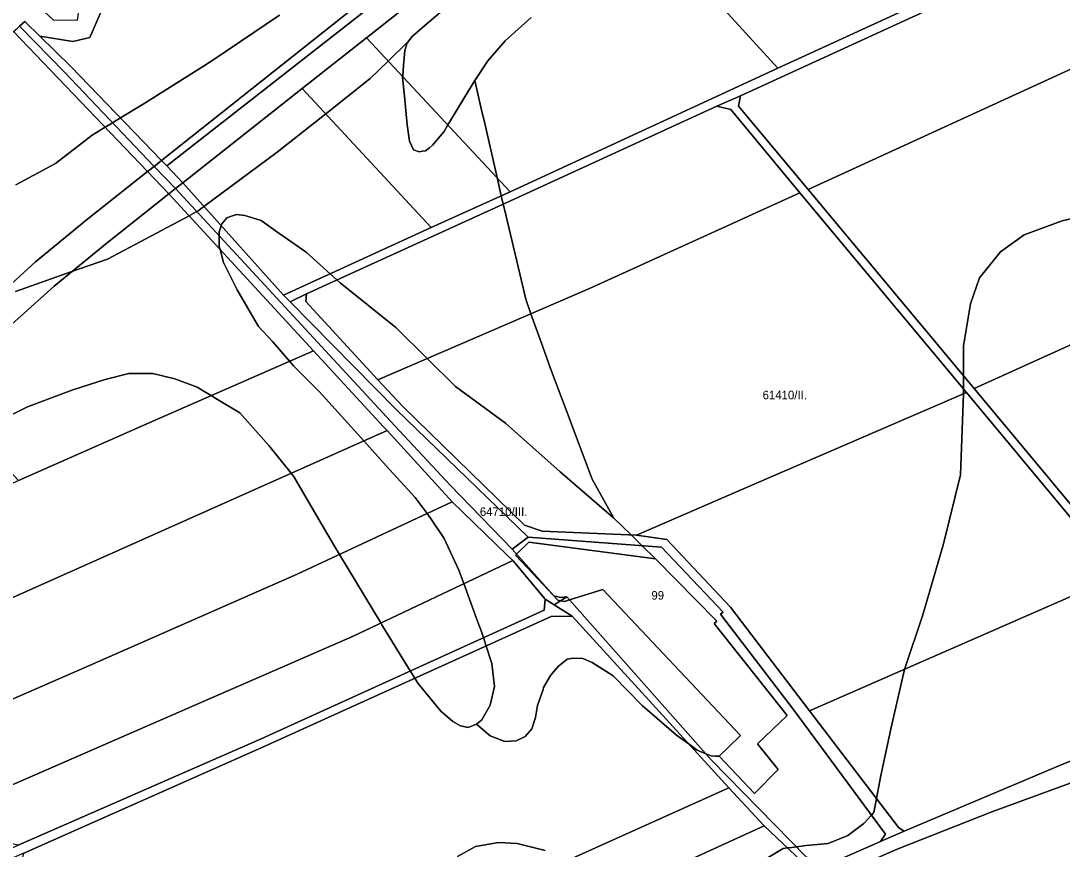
# Model space of a CAD drawing. Extents: x -522079 to -518833, y -1142400 to -1139961.
# Drawn here: x -521596 to -520985, y -1141010 to -1140524 of the extents above; entities that cross this region are included whole.
import ezdxf

# ---------------------------------------------------------------- set-up
doc = ezdxf.new("R2010")
doc.units = 0
for name, color, linetype in [('95560013', 7, 'Continuous'), ('95610013', 7, 'Continuous'), ('95620013', 7, 'Continuous'), ('95630013', 7, 'Continuous'), ('95640013', 7, 'Continuous'), ('95660013', 7, 'Continuous')]:
    doc.layers.add(name, color=color, linetype=linetype)

msp = doc.modelspace()

# ---------------------------------------------------------------- linework, layer by layer
at = {"layer": '95560013'}
for points in [[(-521042, -1140261.25), (-521029.36, -1140265.01), (-521071.25, -1140292.13), (-521105.44, -1140313.39), (-521138.04, -1140336), (-521166.55, -1140356.84), (-521170.88, -1140360.01), (-521186.8, -1140371.65), (-521202.24, -1140382.94), (-521262.52, -1140430.5), (-521393.25, -1140533.65), (-521431, -1140563.44), (-521501.14, -1140618.78), (-521510.5, -1140608.85), (-521177.32, -1140348.18), (-521127.62, -1140312.94), (-521125.23, -1140315.3), (-521106.97, -1140303.78), (-521080.73, -1140284.42), (-521065.28, -1140272.43), (-521054.61, -1140266.48)], [(-521060.49, -1140509.3), (-521152, -1140551.52), (-521262.52, -1140430.5), (-521202.24, -1140382.94), (-521186.8, -1140371.65)], [(-521309.07, -1140623.96), (-521393.25, -1140533.65), (-521262.52, -1140430.5), (-521152, -1140551.52)], [(-521174.07, -1140567.72), (-521038.29, -1140505.39), (-520903.84, -1140443.54), (-520902.4, -1140445.74), (-520890.58, -1140462.46), (-520871.65, -1140486.28), (-520862.22, -1140497.87), (-521134.28, -1140622.71), (-521175.11, -1140573.76)], [(-520862.22, -1140497.87), (-520765.71, -1140616.57), (-520897.82, -1140676.39), (-521036.95, -1140739.4), (-521134.28, -1140622.71)], [(-521521.75, -1140612.22), (-521600.31, -1140530.11), (-521598.04, -1140528.01), (-521596.8, -1140526.87), (-521570.34, -1140553.98), (-521517.85, -1140609.14)], [(-521587.52, -1140665.2), (-521613.36, -1140688.64), (-521670.89, -1140604.59), (-521650.96, -1140608.19), (-521643.99, -1140618.34), (-521635.78, -1140620.38), (-521621.47, -1140616.67), (-521618.3, -1140572.85), (-521633.5, -1140565.29), (-521616.47, -1140556.14), (-521611.96, -1140540.86), (-521600.31, -1140530.11), (-521521.75, -1140612.22), (-521556.8, -1140639.91)], [(-521309.07, -1140623.96), (-521355.48, -1140644.9), (-521431, -1140563.44), (-521393.25, -1140533.65)], [(-521431, -1140563.44), (-521355.48, -1140644.9), (-521441.99, -1140684.63), (-521501.14, -1140618.78)], [(-521187.8, -1140573.75), (-521174.07, -1140567.72), (-521175.11, -1140573.76), (-521134.28, -1140622.71), (-521036.95, -1140739.4), (-520947.33, -1140846.85), (-520890.08, -1140915.49), (-520882.47, -1140917.37), (-520896.33, -1140923.45), (-520894.6, -1140917.89), (-520952.05, -1140848.96), (-521041.47, -1140741.65), (-521139.09, -1140624.65), (-521179.71, -1140575.8)], [(-521428.47, -1140683.93), (-521306.81, -1140628.37), (-521187.8, -1140573.75), (-521179.71, -1140575.8), (-521139.09, -1140624.65), (-521262.57, -1140680.65), (-521386.59, -1140734.32), (-521428.9, -1140688.4)], [(-521036.95, -1140739.4), (-520897.82, -1140676.39), (-520765.71, -1140616.57), (-520757.18, -1140627.06), (-520745.42, -1140642.26), (-520733.42, -1140657.97), (-520724.12, -1140671.61), (-520771, -1140692.05), (-520722.34, -1140745.4), (-520809.38, -1140784.65), (-520947.33, -1140846.85)], [(-521424.45, -1140717.21), (-521517.19, -1140758), (-521597.52, -1140793.25), (-521643.56, -1140744), (-521605.53, -1140705.44), (-521576.52, -1140679.31), (-521545.43, -1140654.05), (-521509.24, -1140625.15)], [(-521386.59, -1140734.32), (-521262.57, -1140680.65), (-521139.09, -1140624.65), (-521041.47, -1140741.65), (-521164.66, -1140794.98), (-521234.98, -1140825.42), (-521290.3, -1140823.03), (-521300.72, -1140819.47), (-521372.2, -1140749.84)], [(-521589.34, -1140856.91), (-521690.16, -1140901.59), (-521731.35, -1140851.98), (-521597.52, -1140793.25), (-521517.19, -1140758), (-521424.45, -1140717.21), (-521383.31, -1140761.88), (-521381.12, -1140763.92), (-521473.38, -1140805.12)], [(-521234.98, -1140825.42), (-521164.66, -1140794.98), (-521041.47, -1140741.65), (-520952.05, -1140848.96), (-521133.42, -1140928.49), (-521179.82, -1140867.68), (-521217.11, -1140828.01)], [(-521589.34, -1140856.91), (-521473.38, -1140805.12), (-521381.12, -1140763.92), (-521343.03, -1140805.79), (-521433.97, -1140848.31), (-521555.85, -1140901.74), (-521654.5, -1140944.84), (-521662.84, -1140934.49), (-521690.16, -1140901.59)], [(-521343.03, -1140805.79), (-521311.05, -1140836.96), (-521307.59, -1140840.17), (-521401.58, -1140884.75), (-521526.28, -1140939.14), (-521624.6, -1140981.98), (-521654.5, -1140944.84), (-521555.85, -1140901.74), (-521433.97, -1140848.31)], [(-521526.28, -1140939.14), (-521401.58, -1140884.75), (-521307.59, -1140840.17), (-521288.46, -1140863.02), (-521289.17, -1140869.28), (-521455.15, -1140944.86), (-521597.65, -1141007.23), (-521605.69, -1141005.48), (-521624.6, -1140981.98)], [(-521133.42, -1140928.49), (-520952.05, -1140848.96), (-520894.6, -1140917.89), (-520896.33, -1140923.45), (-520987.34, -1140960.66), (-521077.97, -1140999.02), (-521081.12, -1140996.97)], [(-521288.46, -1140863.02), (-521283.24, -1140866.3), (-521272.67, -1140872.95), (-521285.04, -1140873.12), (-521453.3, -1140949.4), (-521594.31, -1141011.83), (-521607.81, -1141017.81), (-521735.67, -1141074.42), (-521844.44, -1141121.41), (-521845.59, -1141127.96), (-521855.85, -1141115.33), (-521847.83, -1141117.27), (-521813.35, -1141102.46), (-521737.51, -1141069.87), (-521612.22, -1141013.76), (-521597.65, -1141007.23), (-521455.15, -1140944.86), (-521289.17, -1140869.28)], [(-521453.3, -1140949.4), (-521285.04, -1140873.12), (-521272.67, -1140872.95), (-521180.73, -1140973.62), (-521309.93, -1141031.69), (-521313.87, -1141033.11), (-521404.59, -1141074.2), (-521511.15, -1141120.5), (-521541.57, -1141083.01), (-521595.68, -1141017.57), (-521594.31, -1141011.83)], [(-520895.4, -1141219.71), (-520895.96, -1141221.04), (-521038.45, -1141284.46), (-521072.62, -1141164.33), (-521112.83, -1141022.98), (-521082.18, -1141009.47), (-521026.59, -1140987.63), (-520970.5, -1140967.09), (-520964.29, -1140970.32), (-520927.66, -1141102.94)], [(-521296.08, -1141050.04), (-521285.67, -1141044.64), (-521289.36, -1141034.73), (-521302.83, -1141040.76), (-521309.93, -1141031.69), (-521180.73, -1140973.62), (-521160.03, -1140995.91), (-521291.39, -1141055.81)], [(-521134.18, -1141024.63), (-521223.67, -1141064.26), (-521262.72, -1141081.47), (-521271.3, -1141080.74), (-521291.39, -1141055.81), (-521160.03, -1140995.91), (-521134.23, -1141020.21)]]:
    msp.add_lwpolyline(points, close=True, dxfattribs=at)
msp.add_lwpolyline([(-521613.36, -1140688.64), (-521587.52, -1140665.2), (-521556.8, -1140639.91), (-521521.75, -1140612.22), (-521509.24, -1140625.15), (-521545.43, -1140654.05), (-521576.52, -1140679.31), (-521605.53, -1140705.44)], dxfattribs=at)
at = {"layer": '95610013'}
msp.add_lwpolyline([(-521389.53, -1140507.12), (-521513.48, -1140605.69), (-521566.82, -1140550.59), (-521584.91, -1140532.83), (-521565.66, -1140535.94), (-521555.6, -1140533.49), (-521549.24, -1140518.67), (-521549.91, -1140499.85), (-521541.79, -1140492.15), (-521495.23, -1140479.84), (-521471.95, -1140488.22), (-521462.16, -1140502.96), (-521450.52, -1140503.04), (-521437.98, -1140472.83), (-521435.8, -1140458.35)], close=True, dxfattribs=at)
at = {"layer": '95620013'}
msp.add_lwpolyline([(-521283.37, -1140860.94), (-521307.86, -1140833.61), (-521298.55, -1140826.47), (-521220.23, -1140832.37), (-521184.18, -1140870.5), (-521185.72, -1140871.68), (-521143.12, -1140927.46), (-521088.9, -1141000.66), (-521091.97, -1141005.03), (-521120.79, -1141017.67), (-521135.25, -1141014.2), (-521191.17, -1140957.11), (-521275.9, -1140861.47), (-521279.53, -1140861.89)], close=True, dxfattribs=at)
at = {"layer": '95630013'}
msp.add_lwpolyline([(-521606.9, -1140511.13), (-521592.51, -1140508.64), (-521577.07, -1140523.11), (-521562.91, -1140523.45), (-521557.78, -1140487.71), (-521540.23, -1140479.04), (-521496.06, -1140465.78), (-521465.61, -1140476.61), (-521468.11, -1140480.32), (-521471.95, -1140488.22), (-521495.23, -1140479.84), (-521541.79, -1140492.15), (-521549.91, -1140499.85), (-521549.24, -1140518.67), (-521555.6, -1140533.49), (-521565.66, -1140535.94), (-521584.91, -1140532.83), (-521593.79, -1140524.1), (-521596.8, -1140526.87)], dxfattribs=at)
for points in [[(-521513.48, -1140605.69), (-521517.85, -1140609.14), (-521570.34, -1140553.98), (-521596.8, -1140526.87), (-521593.79, -1140524.1), (-521584.91, -1140532.83), (-521566.82, -1140550.59)], [(-521517.85, -1140609.14), (-521513.48, -1140605.69), (-521510.5, -1140608.85), (-521501.14, -1140618.78), (-521505.44, -1140622.18)], [(-521501.14, -1140618.78), (-521441.99, -1140684.63), (-521438.02, -1140688.47), (-521375.87, -1140751.79), (-521298.55, -1140826.47), (-521307.86, -1140833.61), (-521344.11, -1140796.22), (-521379.23, -1140758.51), (-521505.44, -1140622.18)]]:
    msp.add_lwpolyline(points, close=True, dxfattribs=at)
at = {"layer": '95640013'}
for points in [[(-521245.45, -1140392.88), (-521233.39, -1140383.74), (-521212.85, -1140368.17), (-521190.73, -1140351.49), (-521181.05, -1140344.19), (-521160.13, -1140329.24), (-521148.51, -1140320.94), (-521130.86, -1140309.33), (-521127.62, -1140312.94), (-521177.32, -1140348.18), (-521510.5, -1140608.85), (-521513.48, -1140605.69), (-521389.53, -1140507.12), (-521274.04, -1140415.55), (-521252.22, -1140398.25)], [(-521428.47, -1140683.93), (-521438.02, -1140688.47), (-521441.99, -1140684.63), (-521355.48, -1140644.9), (-521309.07, -1140623.96), (-521152, -1140551.52), (-521060.49, -1140509.3), (-521045.09, -1140502.65), (-521031.07, -1140496.4), (-520906.37, -1140439.12), (-520903.84, -1140443.54), (-521038.29, -1140505.39), (-521174.07, -1140567.72), (-521187.8, -1140573.75), (-521306.81, -1140628.37)], [(-521521.75, -1140612.22), (-521517.85, -1140609.14), (-521505.44, -1140622.18), (-521509.24, -1140625.15)], [(-521283.37, -1140860.94), (-521279.53, -1140861.89), (-521275.9, -1140861.47), (-521283.24, -1140866.3), (-521288.46, -1140863.02), (-521307.59, -1140840.17), (-521311.05, -1140836.96), (-521343.03, -1140805.79), (-521381.12, -1140763.92), (-521383.31, -1140761.88), (-521424.45, -1140717.21), (-521509.24, -1140625.15), (-521505.44, -1140622.18), (-521379.23, -1140758.51), (-521344.11, -1140796.22), (-521307.86, -1140833.61)], [(-521077.97, -1140999.02), (-521091.97, -1141005.03), (-521088.9, -1141000.66), (-521143.12, -1140927.46), (-521185.72, -1140871.68), (-521184.18, -1140870.5), (-521220.23, -1140832.37), (-521298.55, -1140826.47), (-521375.87, -1140751.79), (-521438.02, -1140688.47), (-521428.47, -1140683.93), (-521428.9, -1140688.4), (-521386.59, -1140734.32), (-521372.2, -1140749.84), (-521300.72, -1140819.47), (-521290.3, -1140823.03), (-521234.98, -1140825.42), (-521217.11, -1140828.01), (-521179.82, -1140867.68), (-521133.42, -1140928.49), (-521081.12, -1140996.97)], [(-521134.18, -1141024.63), (-521134.23, -1141020.21), (-521160.03, -1140995.91), (-521180.73, -1140973.62), (-521272.67, -1140872.95), (-521283.24, -1140866.3), (-521275.9, -1140861.47), (-521191.17, -1140957.11), (-521135.25, -1141014.2), (-521120.79, -1141017.67)]]:
    msp.add_lwpolyline(points, close=True, dxfattribs=at)
for points in [[(-521120.79, -1141017.67), (-521091.97, -1141005.03), (-521077.97, -1140999.02), (-520987.34, -1140960.66), (-520896.33, -1140923.45)], [(-520970.5, -1140967.09), (-521026.59, -1140987.63), (-521082.18, -1141009.47), (-521112.83, -1141022.98)]]:
    msp.add_lwpolyline(points, dxfattribs=at)
at = {"layer": '95660013'}
for points in [[(-521314.13, -1140488.23), (-521359.2, -1140526.55), (-521366.49, -1140533.05), (-521369.36, -1140536.45), (-521369.47, -1140536.57), (-521380.52, -1140547.3), (-521391.21, -1140557.67), (-521417.24, -1140578.28), (-521445.69, -1140600.79), (-521488.72, -1140632.6), (-521488.95, -1140632.77), (-521492.92, -1140635.7), (-521493.16, -1140635.88), (-521497.32, -1140638.09), (-521545.14, -1140663.46), (-521566.13, -1140670.87), (-521599.12, -1140682.51)], [(-521296.83, -1140521.82), (-521311.93, -1140535.49), (-521322.2, -1140547.14), (-521329.76, -1140558.79), (-521335.7, -1140568.27), (-521341.35, -1140577.71), (-521345.58, -1140584.79), (-521347.86, -1140588.59), (-521354.61, -1140596.72), (-521356.45, -1140598.2), (-521358.66, -1140599.98), (-521360.65, -1140600.26), (-521362.44, -1140600.51), (-521365.68, -1140599.43), (-521368.11, -1140594.28), (-521369.46, -1140584.8), (-521371.09, -1140568.03), (-521372.17, -1140556.89), (-521372.12, -1140556.32), (-521371.55, -1140549.74), (-521370.81, -1140541.18), (-521370.09, -1140538.7), (-521369.47, -1140536.57), (-521369.36, -1140536.45), (-521366.49, -1140533.05), (-521359.2, -1140526.55), (-521314.13, -1140488.23)], [(-521617.61, -1140762.73), (-521592.12, -1140750.19), (-521565.63, -1140740.17), (-521546.64, -1140734.15), (-521532.65, -1140730.64), (-521518.65, -1140730.64), (-521505.66, -1140733.65), (-521492.66, -1140738.66), (-521488.19, -1140741.31), (-521484.39, -1140743.57), (-521481.67, -1140745.18), (-521467.68, -1140753.7), (-521450.68, -1140772.76), (-521437.48, -1140789.09), (-521435.69, -1140791.31), (-521422.65, -1140813.77), (-521412.7, -1140830.91), (-521409.2, -1140836.73), (-521385.01, -1140876.89), (-521384.36, -1140877.96), (-521383.71, -1140879.04), (-521367.63, -1140905.01), (-521364.95, -1140909.34), (-521363.22, -1140912.13), (-521349.73, -1140928.68), (-521342.73, -1140934.69), (-521338.23, -1140937.2), (-521333.73, -1140938.2), (-521328.74, -1140936.19), (-521320.79, -1140943.14), (-521312.14, -1140946.39), (-521305.48, -1140946.03), (-521300.25, -1140943.5), (-521296.46, -1140938.98), (-521294.12, -1140932.29), (-521293.04, -1140925.24), (-521289.8, -1140915.81), (-521289.44, -1140914.76), (-521285.47, -1140907.71), (-521283.3, -1140905.19), (-521280.79, -1140902.28), (-521277.8, -1140899.91), (-521275.56, -1140898.13), (-521273.3, -1140897.78), (-521271.96, -1140897.58), (-521266.37, -1140897.76), (-521260.96, -1140900.11), (-521248.71, -1140907.89), (-521231.59, -1140925.24), (-521211.59, -1140942.6), (-521204.15, -1140947.97), (-521199.33, -1140951.45), (-521194.28, -1140953.59), (-521191.22, -1140954.89), (-521188.61, -1140954.99), (-521186.59, -1140955.07), (-521165.77, -1140976.98), (-521151.91, -1140962.84), (-521163.92, -1140947.73), (-521146.54, -1140931.11), (-521189.38, -1140877.12), (-521187.89, -1140875.92), (-521223.91, -1140839.29), (-521231.85, -1140831.49), (-521238.18, -1140825.28), (-521248.27, -1140815.37), (-521260.91, -1140792.54), (-521276.65, -1140750.96), (-521285.44, -1140727.74), (-521290, -1140714.96), (-521296.94, -1140695.52), (-521299.96, -1140687.05), (-521312.48, -1140634.31), (-521313.18, -1140631.27), (-521314.31, -1140626.33), (-521316.74, -1140615.73), (-521324, -1140584.08), (-521326.22, -1140574.33), (-521329.76, -1140558.79), (-521322.2, -1140547.14), (-521311.93, -1140535.49), (-521296.83, -1140521.82)], [(-521444.35, -1140520.43), (-521482.31, -1140546.07), (-521488.93, -1140550.27), (-521524.31, -1140572.72), (-521537.62, -1140580.75), (-521542.22, -1140583.53), (-521546.64, -1140586.2), (-521554.17, -1140590.74), (-521575.67, -1140607.49), (-521598.95, -1140619.93)], [(-521598.95, -1140619.93), (-521575.67, -1140607.49), (-521554.17, -1140590.74), (-521546.64, -1140586.2), (-521542.22, -1140583.53), (-521537.62, -1140580.75), (-521524.31, -1140572.72), (-521488.93, -1140550.27), (-521482.31, -1140546.07), (-521444.35, -1140520.43)], [(-521599.12, -1140682.51), (-521566.13, -1140670.87), (-521545.14, -1140663.46), (-521497.32, -1140638.09), (-521493.16, -1140635.88), (-521492.92, -1140635.7), (-521488.95, -1140632.77), (-521488.72, -1140632.6), (-521445.69, -1140600.79), (-521417.24, -1140578.28), (-521391.21, -1140557.67), (-521380.52, -1140547.3), (-521369.47, -1140536.57), (-521370.09, -1140538.7), (-521370.81, -1140541.18), (-521371.55, -1140549.74), (-521372.12, -1140556.32), (-521372.17, -1140556.89), (-521371.09, -1140568.03), (-521369.46, -1140584.8), (-521368.11, -1140594.28), (-521365.68, -1140599.43), (-521362.44, -1140600.51), (-521360.65, -1140600.26), (-521358.66, -1140599.98), (-521356.45, -1140598.2), (-521354.61, -1140596.72), (-521347.86, -1140588.59), (-521345.58, -1140584.79), (-521341.35, -1140577.71), (-521335.7, -1140568.27), (-521329.76, -1140558.79), (-521326.22, -1140574.33), (-521324, -1140584.08), (-521316.74, -1140615.73), (-521314.31, -1140626.33), (-521313.18, -1140631.27), (-521312.48, -1140634.31), (-521299.96, -1140687.05), (-521296.94, -1140695.52), (-521290, -1140714.96), (-521285.44, -1140727.74), (-521276.65, -1140750.96), (-521260.91, -1140792.54), (-521248.27, -1140815.37), (-521279.76, -1140788.29), (-521311.74, -1140759.72), (-521341.23, -1140738.16), (-521357.74, -1140721.83), (-521376.21, -1140703.57), (-521408.7, -1140677.5), (-521410.61, -1140675.77), (-521414.69, -1140672.09), (-521428.69, -1140659.45), (-521446.68, -1140646.92), (-521455.18, -1140640.9), (-521464.68, -1140637.89), (-521469.67, -1140637.39), (-521472.48, -1140638.41), (-521475.17, -1140639.39), (-521478.17, -1140642.91), (-521478.52, -1140643.96), (-521479.67, -1140647.42), (-521479.67, -1140650.01), (-521479.67, -1140655.94), (-521479.19, -1140657.78), (-521477.17, -1140665.46), (-521469.17, -1140681.51), (-521456.68, -1140703.07), (-521448.18, -1140712.09), (-521438.52, -1140723.4), (-521436.19, -1140726.13), (-521421.19, -1140741.17), (-521394.99, -1140770.11), (-521381.71, -1140784.79), (-521364.72, -1140803.34), (-521357.74, -1140812.67), (-521355.72, -1140815.37), (-521347.73, -1140827.4), (-521339.23, -1140845.95), (-521336.34, -1140853.8), (-521328.03, -1140876.34), (-521325.74, -1140882.55), (-521324.76, -1140885.49), (-521323.13, -1140890.39), (-521319.74, -1140900.6), (-521318.24, -1140914.13), (-521320.74, -1140925.17), (-521325.74, -1140933.69), (-521328.74, -1140936.19), (-521333.73, -1140938.2), (-521338.23, -1140937.2), (-521342.73, -1140934.69), (-521349.73, -1140928.68), (-521363.22, -1140912.13), (-521364.95, -1140909.34), (-521367.63, -1140905.01), (-521383.71, -1140879.04), (-521384.36, -1140877.96), (-521385.01, -1140876.89), (-521409.2, -1140836.73), (-521412.7, -1140830.91), (-521422.65, -1140813.77), (-521435.69, -1140791.31), (-521437.48, -1140789.09), (-521450.68, -1140772.76), (-521467.68, -1140753.7), (-521481.67, -1140745.18), (-521484.39, -1140743.57), (-521488.19, -1140741.31), (-521492.66, -1140738.66), (-521505.66, -1140733.65), (-521518.65, -1140730.64), (-521532.65, -1140730.64), (-521546.64, -1140734.15), (-521565.63, -1140740.17), (-521592.12, -1140750.19), (-521617.61, -1140762.73)], [(-521157.69, -1141014.42), (-521148.92, -1141009.15), (-521146.33, -1141008.81), (-521143.95, -1141008.5), (-521141.19, -1141008.13), (-521135.49, -1141007.39), (-521122.64, -1141006.22), (-521110.95, -1141001.53), (-521101.61, -1140994.5), (-521097.13, -1140989.55), (-521096.08, -1140988.39), (-521095.76, -1140988.05), (-521094.21, -1140979.83), (-521093.05, -1140973.64), (-521091.68, -1140966.37), (-521086.78, -1140943.6), (-521085.25, -1140936.48), (-521077.75, -1140904.08), (-521077.66, -1140903.67), (-521067.14, -1140872.02), (-521054.87, -1140830.42), (-521044.94, -1140789.98), (-521043.29, -1140742.44), (-521043.19, -1140739.59), (-521043.19, -1140731.92), (-521043.19, -1140714.39), (-521039.1, -1140689.78), (-521033.84, -1140674.54), (-521021.58, -1140659.31), (-521007.56, -1140649.34), (-520985.36, -1140641.14), (-520962.58, -1140635.86)], [(-520962.58, -1140635.86), (-520985.36, -1140641.14), (-521007.56, -1140649.34), (-521021.58, -1140659.31), (-521033.84, -1140674.54), (-521039.1, -1140689.78), (-521043.19, -1140714.39), (-521043.19, -1140731.92), (-521043.19, -1140739.59), (-521043.29, -1140742.44), (-521044.94, -1140789.98), (-521054.87, -1140830.42), (-521067.14, -1140872.02), (-521077.66, -1140903.67), (-521077.75, -1140904.08), (-521085.25, -1140936.48), (-521086.78, -1140943.6), (-521091.68, -1140966.37), (-521093.05, -1140973.64), (-521094.21, -1140979.83), (-521095.76, -1140988.05), (-521096.08, -1140988.39), (-521097.13, -1140989.55), (-521101.61, -1140994.5), (-521110.95, -1141001.53), (-521122.64, -1141006.22), (-521135.49, -1141007.39), (-521141.19, -1141008.13), (-521143.95, -1141008.5), (-521146.33, -1141008.81), (-521148.92, -1141009.15), (-521157.69, -1141014.42)], [(-521339.94, -1141013.83), (-521329.43, -1141007.98), (-521315.99, -1141005.63), (-521304.89, -1141006.22), (-521288.54, -1141010.32)], [(-521288.54, -1141010.32), (-521304.89, -1141006.22), (-521315.99, -1141005.63), (-521329.43, -1141007.98), (-521339.94, -1141013.83)]]:
    msp.add_lwpolyline(points, dxfattribs=at)
for points in [[(-521248.27, -1140815.37), (-521238.18, -1140825.28), (-521231.85, -1140831.49), (-521223.91, -1140839.29), (-521298.04, -1140829.45), (-521305.29, -1140836.48), (-521305.94, -1140837.11), (-521295.62, -1140848.04), (-521281.03, -1140863.48), (-521279.48, -1140863.83), (-521277.13, -1140864.35), (-521274.18, -1140863.41), (-521254.67, -1140857.19), (-521174.02, -1140942.81), (-521174.64, -1140943.41), (-521186.59, -1140955.07), (-521188.61, -1140954.99), (-521191.22, -1140954.89), (-521194.28, -1140953.59), (-521199.33, -1140951.45), (-521204.15, -1140947.97), (-521211.59, -1140942.6), (-521231.59, -1140925.24), (-521248.71, -1140907.89), (-521260.96, -1140900.11), (-521266.37, -1140897.76), (-521271.96, -1140897.58), (-521273.3, -1140897.78), (-521275.56, -1140898.13), (-521277.8, -1140899.91), (-521280.79, -1140902.28), (-521283.3, -1140905.19), (-521285.47, -1140907.71), (-521289.44, -1140914.76), (-521289.8, -1140915.81), (-521293.04, -1140925.24), (-521294.12, -1140932.29), (-521296.46, -1140938.98), (-521300.25, -1140943.5), (-521305.48, -1140946.03), (-521312.14, -1140946.39), (-521320.79, -1140943.14), (-521328.74, -1140936.19), (-521325.74, -1140933.69), (-521320.74, -1140925.17), (-521318.24, -1140914.13), (-521319.74, -1140900.6), (-521323.13, -1140890.39), (-521324.76, -1140885.49), (-521325.74, -1140882.55), (-521328.03, -1140876.34), (-521336.34, -1140853.8), (-521339.23, -1140845.95), (-521347.73, -1140827.4), (-521355.72, -1140815.37), (-521357.74, -1140812.67), (-521364.72, -1140803.34), (-521381.71, -1140784.79), (-521394.99, -1140770.11), (-521421.19, -1140741.17), (-521436.19, -1140726.13), (-521438.52, -1140723.4), (-521448.18, -1140712.09), (-521456.68, -1140703.07), (-521469.17, -1140681.51), (-521477.17, -1140665.46), (-521479.19, -1140657.78), (-521479.67, -1140655.94), (-521479.67, -1140650.01), (-521479.67, -1140647.42), (-521478.52, -1140643.96), (-521478.17, -1140642.91), (-521475.17, -1140639.39), (-521472.48, -1140638.41), (-521469.67, -1140637.39), (-521464.68, -1140637.89), (-521455.18, -1140640.9), (-521446.68, -1140646.92), (-521428.69, -1140659.45), (-521414.69, -1140672.09), (-521410.61, -1140675.77), (-521408.7, -1140677.5), (-521376.21, -1140703.57), (-521357.74, -1140721.83), (-521341.23, -1140738.16), (-521311.74, -1140759.72), (-521279.76, -1140788.29)], [(-521223.91, -1140839.29), (-521187.89, -1140875.92), (-521189.38, -1140877.12), (-521146.54, -1140931.11), (-521163.92, -1140947.73), (-521151.91, -1140962.84), (-521165.77, -1140976.98), (-521186.59, -1140955.07), (-521174.64, -1140943.41), (-521174.02, -1140942.81), (-521254.67, -1140857.19), (-521274.18, -1140863.41), (-521277.13, -1140864.35), (-521279.48, -1140863.83), (-521281.03, -1140863.48), (-521295.62, -1140848.04), (-521305.94, -1140837.11), (-521305.29, -1140836.48), (-521298.04, -1140829.45)]]:
    msp.add_lwpolyline(points, close=True, dxfattribs=at)

# ---------------------------------------------------------------- texts
for s, rotation, p in [('61410/II.', 360, (-521161.02, -1140745.69)), ('64710/III.', 360, (-521326.85, -1140814.12)), ('99', 0, (-521226.24, -1140863.18))]:
    msp.add_text(s, height=5, rotation=rotation, dxfattribs=at).set_placement(p)

doc.saveas('drawing.dxf')
